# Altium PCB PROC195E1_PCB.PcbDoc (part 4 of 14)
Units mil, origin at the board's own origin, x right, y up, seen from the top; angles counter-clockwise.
Board outline 3110.24 x 2500 mil, 10 copper layers (Top Layer, L02_GND1, L03_SIG1, L04_GND2, L05_PWR1, L06_PWR2, L07_GND3, L08_SIG2, L09_GND4, Bottom Layer), stack 66.407 mil thick; 571 components, 538 nets, 6726 pads, 1286 vias.
Unrouted connection lines stored in the file: 4.
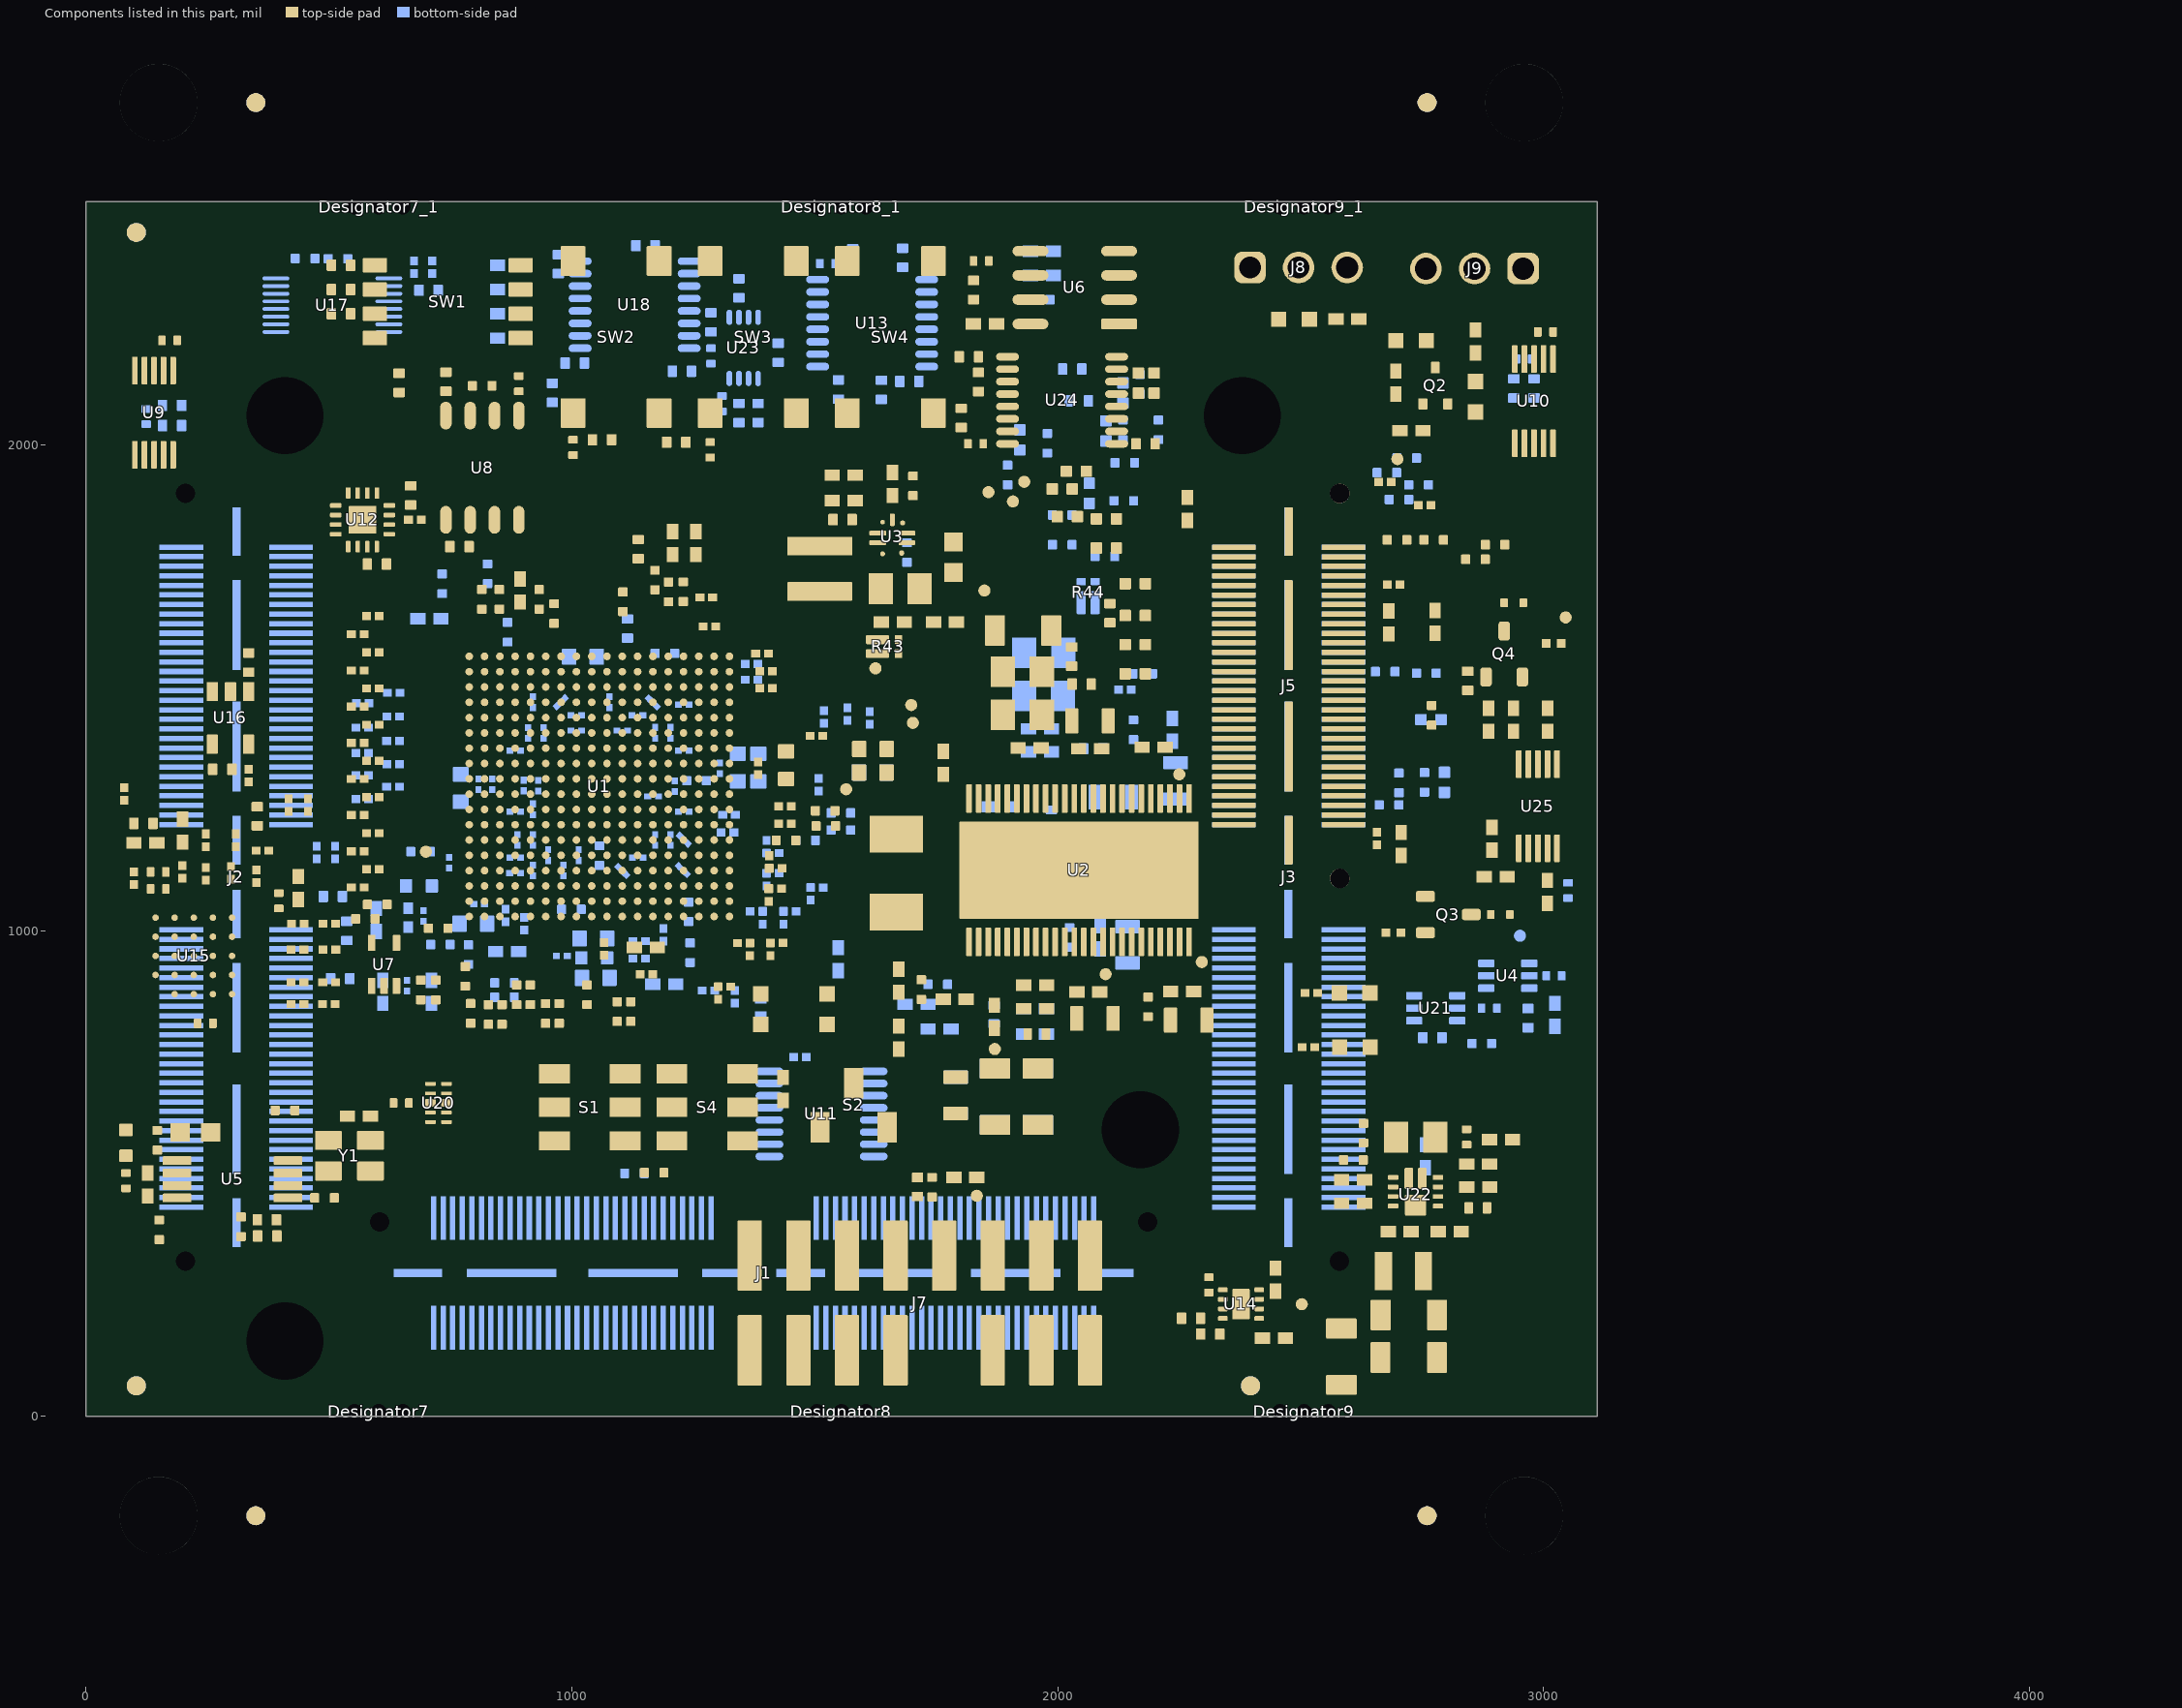
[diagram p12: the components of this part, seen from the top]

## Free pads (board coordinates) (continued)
  round 2.5 on Mech16: 1(163.27,426.27) 1(163.27,426.27) 1(163.27,432.27) 1(163.27,432.27) 1(163.27,445.96) 1(163.27,445.96) 1(163.27,451.96) 1(163.27,451.96) 1(163.27,465.65) 1(163.27,465.65) 1(163.27,471.65) 1(163.27,471.65) 1(163.27,485.34) 1(163.27,485.34) 1(163.27,491.34) 1(163.27,491.34) 1(163.27,505.03) 1(163.27,505.03) 1(163.27,511.03) 1(163.27,511.03) 1(163.27,524.72) 1(163.27,524.72) 1(163.27,530.72) 1(163.27,530.72) 1(163.27,544.41) 1(163.27,544.41) 1(163.27,550.41) 1(163.27,550.41) 1(163.27,564.1) 1(163.27,564.1) 1(163.27,570.1) 1(163.27,570.1) 1(163.27,583.79) 1(163.27,583.79) 1(163.27,589.79) 1(163.27,589.79) 1(163.27,603.48) 1(163.27,603.48) 1(163.27,603.53) 1(163.27,603.53) 1(163.27,609.48) 1(163.27,609.48) 1(163.27,609.53) 1(163.27,609.53) 1(163.27,623.17) 1(163.27,623.17) 1(163.27,629.17) 1(163.27,629.17) 1(163.27,642.86) 1(163.27,642.86) 1(163.27,648.86) 1(163.27,648.86) 1(163.27,662.55) 1(163.27,662.55) 1(163.27,668.55) 1(163.27,668.55) 1(163.27,682.24) 1(163.27,682.24) 1(163.27,688.24) 1(163.27,688.24) 1(163.27,701.93) 1(163.27,701.93) 1(163.27,707.93) 1(163.27,707.93) 1(163.27,721.62) 1(163.27,721.62) 1(163.27,727.62) 1(163.27,727.62) 1(163.27,741.31) 1(163.27,741.31) 1(163.27,747.31) 1(163.27,747.31) 1(163.27,761) 1(163.27,761) 1(163.27,767) 1(163.27,767) 1(163.27,780.69) 1(163.27,780.69) 1(163.27,786.69) 1(163.27,786.69) 1(163.27,800.38) 1(163.27,800.38) 1(163.27,806.38) 1(163.27,806.38) 1(163.27,820.07) 1(163.27,820.07) 1(163.27,826.07) 1(163.27,826.07) 1(163.27,839.76) 1(163.27,839.76) 1(163.27,845.76) 1(163.27,845.76) 1(163.27,859.45) 1(163.27,859.45) 1(163.27,865.45) 1(163.27,865.45) 1(163.27,879.14) 1(163.27,879.14) 1(163.27,885.14) 1(163.27,885.14) 1(163.27,898.83) 1(163.27,898.83) 1(163.27,904.83) 1(163.27,904.83) 1(163.27,918.52) 1(163.27,918.52) 1(163.27,924.52) 1(163.27,924.52) 1(163.27,938.21) 1(163.27,938.21) 1(163.27,944.21) 1(163.27,944.21) 1(163.27,957.9) 1(163.27,957.9) 1(163.27,963.9) 1(163.27,963.9) 1(163.27,977.59) 1(163.27,977.59) 1(163.27,983.59) 1(163.27,983.59) 1(163.27,997.28) 1(163.27,997.28) 1(163.27,1003.28) 1(163.27,1003.28) 1(163.27,1213.77) 1(163.27,1213.77) 1(163.27,1219.77) 1(163.27,1219.77) 1(163.27,1233.46) 1(163.27,1233.46) 1(163.27,1239.46) 1(163.27,1239.46) 1(163.27,1253.15) 1(163.27,1253.15) 1(163.27,1259.15) 1(163.27,1259.15) 1(163.27,1272.84) 1(163.27,1272.84) 1(163.27,1278.84) 1(163.27,1278.84) 1(163.27,1292.53) 1(163.27,1292.53) 1(163.27,1298.53) 1(163.27,1298.53) 1(163.27,1312.22) 1(163.27,1312.22) 1(163.27,1318.22) 1(163.27,1318.22) 1(163.27,1331.91) 1(163.27,1331.91) 1(163.27,1337.91) 1(163.27,1337.91) 1(163.27,1351.6) 1(163.27,1351.6) 1(163.27,1357.6) 1(163.27,1357.6) 1(163.27,1371.29) 1(163.27,1371.29) 1(163.27,1377.29) 1(163.27,1377.29) 1(163.27,1390.98) 1(163.27,1390.98) 1(163.27,1396.98) 1(163.27,1396.98) 1(163.27,1410.67) 1(163.27,1410.67) 1(163.27,1416.67) 1(163.27,1416.67) 1(163.27,1430.36) 1(163.27,1430.36) 1(163.27,1436.36) 1(163.27,1436.36) 1(163.27,1450.05) 1(163.27,1450.05) 1(163.27,1456.05) 1(163.27,1456.05) 1(163.27,1469.74) 1(163.27,1469.74) 1(163.27,1475.74) 1(163.27,1475.74) 1(163.27,1489.43) 1(163.27,1489.43) 1(163.27,1495.43) 1(163.27,1495.43) 1(163.27,1509.12) 1(163.27,1509.12) 1(163.27,1515.12) 1(163.27,1515.12) 1(163.27,1528.81) 1(163.27,1528.81) 1(163.27,1534.81) 1(163.27,1534.81) 1(163.27,1548.5) 1(163.27,1548.5) 1(163.27,1554.5) 1(163.27,1554.5) 1(163.27,1568.19) 1(163.27,1568.19) 1(163.27,1574.19) 1(163.27,1574.19) 1(163.27,1587.88) 1(163.27,1587.88) 1(163.27,1593.88) 1(163.27,1593.88) 1(163.27,1607.57) 1(163.27,1607.57) 1(163.27,1613.57) 1(163.27,1613.57) 1(163.27,1627.26) 1(163.27,1627.26) 1(163.27,1633.26) 1(163.27,1633.26) 1(163.27,1646.95) 1(163.27,1646.95) 1(163.27,1652.95) 1(163.27,1652.95) 1(163.27,1666.64) 1(163.27,1666.64) 1(163.27,1672.64) 1(163.27,1672.64) 1(163.27,1686.33) 1(163.27,1686.33) 1(163.27,1692.33) 1(163.27,1692.33) 1(163.27,1706.02) 1(163.27,1706.02) 1(163.27,1712.02) 1(163.27,1712.02) 1(163.27,1725.71) 1(163.27,1725.71) 1(163.27,1731.71) 1(163.27,1731.71) 1(163.27,1745.4) 1(163.27,1745.4) 1(163.27,1751.4) 1(163.27,1751.4) 1(163.27,1765.09) 1(163.27,1765.09) 1(163.27,1771.09) 1(163.27,1771.09) 1(163.27,1784.78) 1(163.27,1784.78) 1(163.27,1790.78) 1(163.27,1790.78) 1(168.27,296.02) 1(168.27,296.02) 1(168.27,426.27) 1(168.27,432.27) 1(168.27,445.96) 1(168.27,451.96) 1(168.27,465.65) 1(168.27,471.65) 1(168.27,485.34) 1(168.27,491.34) 1(168.27,505.03) 1(168.27,511.03) 1(168.27,524.72) 1(168.27,530.72) 1(168.27,544.41) 1(168.27,550.41) 1(168.27,564.1) 1(168.27,570.1) 1(168.27,583.79) 1(168.27,589.79) 1(168.27,603.48) 1(168.27,603.53) 1(168.27,609.48) 1(168.27,609.53) 1(168.27,623.17) 1(168.27,629.17) 1(168.27,642.86) 1(168.27,648.86) 1(168.27,662.55) 1(168.27,668.55) 1(168.27,682.24) 1(168.27,688.24) 1(168.27,701.93) 1(168.27,707.93) 1(168.27,721.62) 1(168.27,727.62) 1(168.27,741.31) 1(168.27,747.31) 1(168.27,761) 1(168.27,767) 1(168.27,780.69) 1(168.27,786.69) 1(168.27,800.38) 1(168.27,806.38) 1(168.27,820.07) 1(168.27,826.07) 1(168.27,839.76) 1(168.27,845.76) 1(168.27,859.45) 1(168.27,865.45) 1(168.27,879.14) 1(168.27,885.14) 1(168.27,898.83) 1(168.27,904.83) 1(168.27,918.52) 1(168.27,924.52) 1(168.27,938.21) 1(168.27,944.21) 1(168.27,957.9) 1(168.27,963.9) 1(168.27,977.59) 1(168.27,983.59) 1(168.27,997.28) 1(168.27,1003.28) 1(168.27,1213.77) 1(168.27,1219.77) 1(168.27,1233.46) 1(168.27,1239.46) 1(168.27,1253.15) 1(168.27,1259.15) 1(168.27,1272.84) 1(168.27,1278.84) 1(168.27,1292.53) 1(168.27,1298.53) 1(168.27,1312.22) 1(168.27,1318.22) 1(168.27,1331.91) 1(168.27,1337.91) 1(168.27,1351.6) 1(168.27,1357.6) 1(168.27,1371.29) 1(168.27,1377.29) 1(168.27,1390.98) 1(168.27,1396.98) 1(168.27,1410.67) 1(168.27,1416.67) 1(168.27,1430.36) 1(168.27,1436.36) 1(168.27,1450.05) 1(168.27,1456.05) 1(168.27,1469.74) 1(168.27,1475.74) 1(168.27,1489.43) 1(168.27,1495.43) 1(168.27,1509.12) 1(168.27,1515.12) 1(168.27,1528.81) 1(168.27,1534.81) 1(168.27,1548.5) 1(168.27,1554.5) 1(168.27,1568.19) 1(168.27,1574.19) 1(168.27,1587.88) 1(168.27,1593.88) 1(168.27,1607.57) 1(168.27,1613.57) 1(168.27,1627.26) 1(168.27,1633.26) 1(168.27,1646.95) 1(168.27,1652.95) 1(168.27,1666.64) 1(168.27,1672.64) 1(168.27,1686.33) 1(168.27,1692.33) 1(168.27,1706.02) 1(168.27,1712.02) 1(168.27,1725.71) 1(168.27,1731.71) 1(168.27,1745.4) 1(168.27,1751.4) 1(168.27,1765.09) 1(168.27,1771.09) 1(168.27,1784.78) 1(168.27,1790.78) 1(168.27,1921.02) 1(168.27,1921.02) 1(176.27,1852) 1(176.27,1852) 1(176.27,1913.02) 1(176.27,1913.02) 1(182.5,370.13) 1(182.5,370.13) 1(182.5,370.13) 1(182.5,1846.92) 1(182.5,1846.92) 1(182.5,1846.92) 1(188.27,372.52) 1(188.27,372.52) 1(188.27,372.52) 1(188.27,1844.52) 1(188.27,1844.52) 1(188.27,1844.52) 1(237.29,1913.02) 1(237.29,1913.02) 1(240.88,311.75) 1(240.88,311.75) 1(240.88,311.75) 1(240.88,1905.3) 1(240.88,1905.3) 1(240.88,1905.3) 1(243.27,317.52) 1(243.27,317.52) 1(243.27,317.52) 1(243.27,1899.52) 1(243.27,1899.52) 1(243.27,1899.52) 1(433.27,317.52) 1(433.27,317.52) 1(433.27,317.52) 1(433.27,1899.52) 1(433.27,1899.52) 1(433.27,1899.52) 1(439.04,311.75) 1(439.04,311.75) 1(439.04,311.75) 1(439.04,1905.3) 1(439.04,1905.3) 1(439.04,1905.3) 1(453.27,296.02) 1(453.27,296.02) 1(453.27,426.27) 1(453.27,432.27) 1(453.27,445.96) 1(453.27,451.96) 1(453.27,465.65) 1(453.27,471.65) 1(453.27,485.34) 1(453.27,491.34) 1(453.27,505.03) 1(453.27,511.03) 1(453.27,524.72) 1(453.27,530.72) 1(453.27,544.41) 1(453.27,550.41) 1(453.27,564.1) 1(453.27,570.1) 1(453.27,583.79) 1(453.27,589.79) 1(453.27,603.48) 1(453.27,603.53) 1(453.27,609.48) 1(453.27,609.53) 1(453.27,623.17) 1(453.27,629.17) 1(453.27,642.86) 1(453.27,648.86) 1(453.27,662.55) 1(453.27,668.55) 1(453.27,682.24) 1(453.27,688.24) 1(453.27,701.93) 1(453.27,707.93) 1(453.27,721.62) 1(453.27,727.62) 1(453.27,741.31) 1(453.27,747.31) 1(453.27,761) 1(453.27,767) 1(453.27,780.69) 1(453.27,786.69) 1(453.27,800.38) 1(453.27,806.38) 1(453.27,820.07) 1(453.27,826.07) 1(453.27,839.76) 1(453.27,845.76) 1(453.27,859.45) 1(453.27,865.45) 1(453.27,879.14) 1(453.27,885.14) 1(453.27,898.83) 1(453.27,904.83) 1(453.27,918.52) 1(453.27,924.52) 1(453.27,938.21) 1(453.27,944.21) 1(453.27,957.9) 1(453.27,963.9) 1(453.27,977.59) 1(453.27,983.59) 1(453.27,997.28) 1(453.27,1003.28) 1(453.27,1213.77) 1(453.27,1219.77) 1(453.27,1233.46) 1(453.27,1239.46) 1(453.27,1253.15) 1(453.27,1259.15) 1(453.27,1272.84) 1(453.27,1278.84) 1(453.27,1292.53) 1(453.27,1298.53) 1(453.27,1312.22) 1(453.27,1318.22) 1(453.27,1331.91) 1(453.27,1337.91) 1(453.27,1351.6) 1(453.27,1357.6) 1(453.27,1371.29) 1(453.27,1377.29) 1(453.27,1390.98) 1(453.27,1396.98) 1(453.27,1410.67) 1(453.27,1416.67) 1(453.27,1430.36) 1(453.27,1436.36) 1(453.27,1450.05) 1(453.27,1456.05) 1(453.27,1469.74) 1(453.27,1475.74) 1(453.27,1489.43) 1(453.27,1495.43) 1(453.27,1509.12) 1(453.27,1515.12) 1(453.27,1528.81) 1(453.27,1534.81) 1(453.27,1548.5) 1(453.27,1554.5) 1(453.27,1568.19) 1(453.27,1574.19) 1(453.27,1587.88) 1(453.27,1593.88) 1(453.27,1607.57) 1(453.27,1613.57) 1(453.27,1627.26) 1(453.27,1633.26) 1(453.27,1646.95) 1(453.27,1652.95) 1(453.27,1666.64) 1(453.27,1672.64) 1(453.27,1686.33) 1(453.27,1692.33) 1(453.27,1706.02) 1(453.27,1712.02) 1(453.27,1725.71) 1(453.27,1731.71) 1(453.27,1745.4) 1(453.27,1751.4) 1(453.27,1765.09) 1(453.27,1771.09) 1(453.27,1784.78) 1(453.27,1790.78) 1(453.27,1921.02) 1(453.27,1921.02) 1(458.27,426.27) 1(458.27,426.27) 1(458.27,432.27) 1(458.27,432.27) 1(458.27,445.96) 1(458.27,445.96) 1(458.27,451.96) 1(458.27,451.96) 1(458.27,465.65) 1(458.27,465.65) 1(458.27,471.65) 1(458.27,471.65) 1(458.27,485.34) 1(458.27,485.34) 1(458.27,491.34) 1(458.27,491.34) 1(458.27,505.03) 1(458.27,505.03) 1(458.27,511.03) 1(458.27,511.03) 1(458.27,524.72) 1(458.27,524.72) 1(458.27,530.72) 1(458.27,530.72) 1(458.27,544.41) 1(458.27,544.41) 1(458.27,550.41) 1(458.27,550.41) 1(458.27,564.1) 1(458.27,564.1) 1(458.27,570.1) 1(458.27,570.1) 1(458.27,583.79) 1(458.27,583.79) 1(458.27,589.79) 1(458.27,589.79) 1(458.27,603.48) 1(458.27,603.48) 1(458.27,603.53) 1(458.27,603.53) 1(458.27,609.48) 1(458.27,609.48) 1(458.27,609.53) 1(458.27,609.53) 1(458.27,623.17) 1(458.27,623.17) 1(458.27,629.17) 1(458.27,629.17) 1(458.27,642.86) 1(458.27,642.86) 1(458.27,648.86) 1(458.27,648.86) 1(458.27,662.55) 1(458.27,662.55) 1(458.27,668.55) 1(458.27,668.55) 1(458.27,682.24) 1(458.27,682.24) 1(458.27,688.24) 1(458.27,688.24) 1(458.27,701.93) 1(458.27,701.93) 1(458.27,707.93) 1(458.27,707.93) 1(458.27,721.62) 1(458.27,721.62) 1(458.27,727.62) 1(458.27,727.62) 1(458.27,741.31) 1(458.27,741.31) 1(458.27,747.31) 1(458.27,747.31) 1(458.27,761) 1(458.27,761) 1(458.27,767) 1(458.27,767) 1(458.27,780.69) 1(458.27,780.69) 1(458.27,786.69) 1(458.27,786.69) 1(458.27,800.38) 1(458.27,800.38) 1(458.27,806.38) 1(458.27,806.38) 1(458.27,820.07) 1(458.27,820.07) 1(458.27,826.07) 1(458.27,826.07) 1(458.27,839.76) 1(458.27,839.76) 1(458.27,845.76) 1(458.27,845.76) 1(458.27,859.45) 1(458.27,859.45) 1(458.27,865.45) 1(458.27,865.45) 1(458.27,879.14) 1(458.27,879.14) 1(458.27,885.14) 1(458.27,885.14) 1(458.27,898.83) 1(458.27,898.83) 1(458.27,904.83) 1(458.27,904.83) 1(458.27,918.52) 1(458.27,918.52) 1(458.27,924.52) 1(458.27,924.52) 1(458.27,938.21) 1(458.27,938.21) 1(458.27,944.21) 1(458.27,944.21) 1(458.27,957.9) 1(458.27,957.9) 1(458.27,963.9) 1(458.27,963.9) 1(458.27,977.59) 1(458.27,977.59) 1(458.27,983.59) 1(458.27,983.59) 1(458.27,997.28) 1(458.27,997.28) 1(458.27,1003.28) 1(458.27,1003.28) 1(458.27,1213.77) 1(458.27,1213.77) 1(458.27,1219.77) 1(458.27,1219.77) 1(458.27,1233.46) 1(458.27,1233.46) 1(458.27,1239.46) 1(458.27,1239.46) 1(458.27,1253.15) 1(458.27,1253.15) 1(458.27,1259.15) 1(458.27,1259.15) 1(458.27,1272.84) 1(458.27,1272.84) 1(458.27,1278.84) 1(458.27,1278.84) 1(458.27,1292.53) 1(458.27,1292.53) 1(458.27,1298.53) 1(458.27,1298.53) 1(458.27,1312.22) 1(458.27,1312.22) 1(458.27,1318.22) 1(458.27,1318.22) 1(458.27,1331.91) 1(458.27,1331.91) 1(458.27,1337.91) 1(458.27,1337.91) 1(458.27,1351.6) 1(458.27,1351.6) 1(458.27,1357.6) 1(458.27,1357.6) 1(458.27,1371.29) 1(458.27,1371.29) 1(458.27,1377.29) 1(458.27,1377.29) 1(458.27,1390.98) 1(458.27,1390.98) 1(458.27,1396.98) 1(458.27,1396.98) 1(458.27,1410.67) 1(458.27,1410.67) 1(458.27,1416.67) 1(458.27,1416.67) 1(458.27,1430.36) 1(458.27,1430.36) 1(458.27,1436.36) 1(458.27,1436.36) 1(458.27,1450.05) 1(458.27,1450.05) 1(458.27,1456.05) 1(458.27,1456.05) 1(458.27,1469.74) 1(458.27,1469.74) 1(458.27,1475.74) 1(458.27,1475.74) 1(458.27,1489.43) 1(458.27,1489.43) 1(458.27,1495.43) 1(458.27,1495.43) 1(458.27,1509.12) 1(458.27,1509.12) 1(458.27,1515.12) 1(458.27,1515.12) 1(458.27,1528.81) 1(458.27,1528.81) 1(458.27,1534.81) 1(458.27,1534.81) 1(458.27,1548.5) 1(458.27,1548.5) 1(458.27,1554.5) 1(458.27,1554.5) 1(458.27,1568.19) 1(458.27,1568.19) 1(458.27,1574.19) 1(458.27,1574.19) 1(458.27,1587.88) 1(458.27,1587.88) 1(458.27,1593.88) 1(458.27,1593.88) 1(458.27,1607.57) 1(458.27,1607.57) 1(458.27,1613.57) 1(458.27,1613.57) 1(458.27,1627.26) 1(458.27,1627.26) 1(458.27,1633.26) 1(458.27,1633.26) 1(458.27,1646.95) 1(458.27,1646.95) 1(458.27,1652.95) 1(458.27,1652.95) 1(458.27,1666.64) 1(458.27,1666.64) 1(458.27,1672.64) 1(458.27,1672.64) 1(458.27,1686.33) 1(458.27,1686.33) 1(458.27,1692.33) 1(458.27,1692.33) 1(458.27,1706.02) 1(458.27,1706.02) 1(458.27,1712.02) 1(458.27,1712.02) 1(458.27,1725.71) 1(458.27,1725.71) 1(458.27,1731.71) 1(458.27,1731.71) 1(458.27,1745.4) 1(458.27,1745.4) 1(458.27,1751.4) 1(458.27,1751.4) 1(458.27,1765.09) 1(458.27,1765.09) 1(458.27,1771.09) 1(458.27,1771.09) 1(458.27,1784.78) 1(458.27,1784.78) 1(458.27,1790.78) 1(458.27,1790.78) 1(581.02,151.73) 1(581.02,151.73) 1(581.02,436.73) 1(581.02,436.73) 1(581.02,1776.73) 1(581.02,1776.73) 1(581.02,2061.73) 1(581.02,2061.73) 1(596.75,165.96) 1(596.75,165.96) 1(596.75,165.96) 1(596.75,364.12) 1(596.75,364.12) 1(596.75,364.12) 1(596.75,1790.96) 1(596.75,1790.96) 1(596.75,1790.96) 1(596.75,1989.12) 1(596.75,1989.12) 1(596.75,1989.12) 1(602.52,171.73) 1(602.52,171.73) 1(602.52,171.73) 1(602.52,361.73) 1(602.52,361.73) 1(602.52,361.73) 1(602.52,1796.73) 1(602.52,1796.73) 1(602.52,1796.73) 1(602.52,1986.73) 1(602.52,1986.73) 1(602.52,1986.73) 1(655.13,422.51) 1(655.13,422.51) 1(655.13,422.51) 1(655.13,2047.51) 1(655.13,2047.51) 1(655.13,2047.51) 1(657.52,416.73) 1(657.52,416.73) 1(657.52,416.73) 1(657.52,2041.73) 1(657.52,2041.73) 1(657.52,2041.73) 1(711.27,146.73) 1(711.27,146.73) 1(711.27,151.73) 1(711.27,436.73) 1(711.27,441.73) 1(711.27,441.73) 1(711.27,1771.73) 1(711.27,1771.73) 1(711.27,1776.73) 1(711.27,2061.73) 1(711.27,2066.73) 1(711.27,2066.73) 1(717.27,146.73) 1(717.27,146.73) 1(717.27,151.73) 1(717.27,436.73) 1(717.27,441.73) 1(717.27,441.73) 1(717.27,1771.73) 1(717.27,1771.73) 1(717.27,1776.73) 1(717.27,2061.73) 1(717.27,2066.73) 1(717.27,2066.73) 1(730.96,146.73) 1(730.96,146.73) 1(730.96,151.73) 1(730.96,436.73) 1(730.96,441.73) 1(730.96,441.73) 1(730.96,1771.73) 1(730.96,1771.73) 1(730.96,1776.73) 1(730.96,2061.73) 1(730.96,2066.73) 1(730.96,2066.73) 1(736.96,146.73) 1(736.96,146.73) 1(736.96,151.73) 1(736.96,436.73) 1(736.96,441.73) 1(736.96,441.73) 1(736.96,1771.73) 1(736.96,1771.73) 1(736.96,1776.73) 1(736.96,2061.73) 1(736.96,2066.73) 1(736.96,2066.73) 1(750.65,146.73) 1(750.65,146.73) 1(750.65,151.73) 1(750.65,436.73) 1(750.65,441.73) 1(750.65,441.73) 1(750.65,1771.73) 1(750.65,1771.73) 1(750.65,1776.73) 1(750.65,2061.73) 1(750.65,2066.73) 1(750.65,2066.73) 1(756.65,146.73) 1(756.65,146.73) 1(756.65,151.73) 1(756.65,436.73) 1(756.65,441.73) 1(756.65,441.73) 1(756.65,1771.73) 1(756.65,1771.73) 1(756.65,1776.73) 1(756.65,2061.73) 1(756.65,2066.73) 1(756.65,2066.73) 1(770.34,146.73) 1(770.34,146.73) 1(770.34,151.73) 1(770.34,436.73) 1(770.34,441.73) 1(770.34,441.73) 1(770.34,1771.73) 1(770.34,1771.73) 1(770.34,1776.73) 1(770.34,2061.73) 1(770.34,2066.73) 1(770.34,2066.73) 1(776.34,146.73) 1(776.34,146.73) 1(776.34,151.73) 1(776.34,436.73) 1(776.34,441.73) 1(776.34,441.73) 1(776.34,1771.73) 1(776.34,1771.73) 1(776.34,1776.73) 1(776.34,2061.73) 1(776.34,2066.73) 1(776.34,2066.73) 1(790.03,146.73) 1(790.03,146.73) 1(790.03,151.73) 1(790.03,436.73) 1(790.03,441.73) 1(790.03,441.73) 1(790.03,1771.73) 1(790.03,1771.73) 1(790.03,1776.73) 1(790.03,2061.73) 1(790.03,2066.73) 1(790.03,2066.73) 1(796.03,146.73) 1(796.03,146.73) 1(796.03,151.73) 1(796.03,436.73) 1(796.03,441.73) 1(796.03,441.73) 1(796.03,1771.73) 1(796.03,1771.73) 1(796.03,1776.73) 1(796.03,2061.73) 1(796.03,2066.73) 1(796.03,2066.73) 1(809.72,146.73) 1(809.72,146.73) 1(809.72,151.73) 1(809.72,436.73) 1(809.72,441.73) 1(809.72,441.73) 1(809.72,1771.73) 1(809.72,1771.73) 1(809.72,1776.73) 1(809.72,2061.73) 1(809.72,2066.73) 1(809.72,2066.73) 1(815.72,146.73) 1(815.72,146.73) 1(815.72,151.73) 1(815.72,436.73) 1(815.72,441.73) 1(815.72,441.73) 1(815.72,1771.73) 1(815.72,1771.73) 1(815.72,1776.73) 1(815.72,2061.73) 1(815.72,2066.73) 1(815.72,2066.73) 1(829.41,146.73) 1(829.41,146.73) 1(829.41,151.73) 1(829.41,436.73) 1(829.41,441.73) 1(829.41,441.73) 1(829.41,1771.73) 1(829.41,1771.73) 1(829.41,1776.73) 1(829.41,2061.73) 1(829.41,2066.73) 1(829.41,2066.73) 1(835.41,146.73) 1(835.41,146.73) 1(835.41,151.73) 1(835.41,436.73) 1(835.41,441.73) 1(835.41,441.73) 1(835.41,1771.73) 1(835.41,1771.73) 1(835.41,1776.73) 1(835.41,2061.73) 1(835.41,2066.73) 1(835.41,2066.73) 1(849.1,146.73) 1(849.1,146.73) 1(849.1,151.73) 1(849.1,436.73) 1(849.1,441.73) 1(849.1,441.73) 1(849.1,1771.73) 1(849.1,1771.73) 1(849.1,1776.73) 1(849.1,2061.73) 1(849.1,2066.73) 1(849.1,2066.73) 1(855.1,146.73) 1(855.1,146.73) 1(855.1,151.73) 1(855.1,436.73) 1(855.1,441.73) 1(855.1,441.73) 1(855.1,1771.73) 1(855.1,1771.73) 1(855.1,1776.73) 1(855.1,2061.73) 1(855.1,2066.73) 1(855.1,2066.73) 1(868.79,146.73) 1(868.79,146.73) 1(868.79,151.73) 1(868.79,436.73) 1(868.79,441.73) 1(868.79,441.73) 1(868.79,1771.73) 1(868.79,1771.73) 1(868.79,1776.73) 1(868.79,2061.73) 1(868.79,2066.73) 1(868.79,2066.73) 1(874.79,146.73) 1(874.79,146.73) 1(874.79,151.73) 1(874.79,436.73) 1(874.79,441.73) 1(874.79,441.73) 1(874.79,1771.73) 1(874.79,1771.73) 1(874.79,1776.73) 1(874.79,2061.73) 1(874.79,2066.73) 1(874.79,2066.73) 1(888.48,146.73) 1(888.48,146.73) 1(888.48,151.73) 1(888.48,436.73) 1(888.48,441.73) 1(888.48,441.73) 1(888.48,1771.73) 1(888.48,1771.73) 1(888.48,1776.73) 1(888.48,2061.73) 1(888.48,2066.73) 1(888.48,2066.73) 1(888.53,146.73) 1(888.53,146.73) 1(888.53,151.73) 1(888.53,436.73) 1(888.53,441.73) 1(888.53,441.73) 1(888.53,1771.73) 1(888.53,1771.73) 1(888.53,1776.73) 1(888.53,2061.73) 1(888.53,2066.73) 1(888.53,2066.73) 1(894.48,146.73) 1(894.48,146.73) 1(894.48,151.73) 1(894.48,436.73) 1(894.48,441.73) 1(894.48,441.73) 1(894.48,1771.73) 1(894.48,1771.73) 1(894.48,1776.73) 1(894.48,2061.73) 1(894.48,2066.73) 1(894.48,2066.73) 1(894.53,146.73) 1(894.53,146.73) 1(894.53,151.73) 1(894.53,436.73) 1(894.53,441.73) 1(894.53,441.73) 1(894.53,1771.73) 1(894.53,1771.73) 1(894.53,1776.73) 1(894.53,2061.73) 1(894.53,2066.73) 1(894.53,2066.73) 1(908.17,146.73) 1(908.17,146.73) 1(908.17,151.73) 1(908.17,436.73) 1(908.17,441.73) 1(908.17,441.73) 1(908.17,1771.73) 1(908.17,1771.73) 1(908.17,1776.73) 1(908.17,2061.73) 1(908.17,2066.73) 1(908.17,2066.73) 1(914.17,146.73) 1(914.17,146.73) 1(914.17,151.73) 1(914.17,436.73) 1(914.17,441.73) 1(914.17,441.73) 1(914.17,1771.73) 1(914.17,1771.73) 1(914.17,1776.73) 1(914.17,2061.73) 1(914.17,2066.73) 1(914.17,2066.73) 1(927.86,146.73) 1(927.86,146.73) 1(927.86,151.73) 1(927.86,436.73) 1(927.86,441.73) 1(927.86,441.73) 1(927.86,1771.73) 1(927.86,1771.73) 1(927.86,1776.73) 1(927.86,2061.73) 1(927.86,2066.73) 1(927.86,2066.73) 1(933.86,146.73) 1(933.86,146.73) 1(933.86,151.73) 1(933.86,436.73) 1(933.86,441.73) 1(933.86,441.73) 1(933.86,1771.73) 1(933.86,1771.73) 1(933.86,1776.73) 1(933.86,2061.73) 1(933.86,2066.73) 1(933.86,2066.73) 1(947.55,146.73) 1(947.55,146.73) 1(947.55,151.73) 1(947.55,436.73) 1(947.55,441.73) 1(947.55,441.73) 1(947.55,1771.73) 1(947.55,1771.73) 1(947.55,1776.73) 1(947.55,2061.73) 1(947.55,2066.73) 1(947.55,2066.73) 1(953.55,146.73) 1(953.55,146.73) 1(953.55,151.73) 1(953.55,436.73) 1(953.55,441.73) 1(953.55,441.73) 1(953.55,1771.73) 1(953.55,1771.73) 1(953.55,1776.73) 1(953.55,2061.73) 1(953.55,2066.73) 1(953.55,2066.73) 1(967.24,146.73) 1(967.24,146.73) 1(967.24,151.73) 1(967.24,436.73) 1(967.24,441.73) 1(967.24,441.73) 1(967.24,1771.73) 1(967.24,1771.73) 1(967.24,1776.73) 1(967.24,2061.73) 1(967.24,2066.73) 1(967.24,2066.73) 1(973.24,146.73) 1(973.24,146.73) 1(973.24,151.73) 1(973.24,436.73) 1(973.24,441.73) 1(973.24,441.73) 1(973.24,1771.73) 1(973.24,1771.73) 1(973.24,1776.73) 1(973.24,2061.73) 1(973.24,2066.73) 1(973.24,2066.73) 1(986.93,146.73) 1(986.93,146.73) 1(986.93,151.73) 1(986.93,436.73) 1(986.93,441.73) 1(986.93,441.73) 1(986.93,1771.73) 1(986.93,1771.73) 1(986.93,1776.73) 1(986.93,2061.73) 1(986.93,2066.73) 1(986.93,2066.73) 1(992.93,146.73) 1(992.93,146.73) 1(992.93,151.73) 1(992.93,436.73) 1(992.93,441.73) 1(992.93,441.73) 1(992.93,1771.73) 1(992.93,1771.73) 1(992.93,1776.73) 1(992.93,2061.73) 1(992.93,2066.73) 1(992.93,2066.73) 1(1006.62,146.73) 1(1006.62,146.73) 1(1006.62,151.73) 1(1006.62,436.73) 1(1006.62,441.73) 1(1006.62,441.73) 1(1006.62,1771.73) 1(1006.62,1771.73) 1(1006.62,1776.73) 1(1006.62,2061.73) 1(1006.62,2066.73) 1(1006.62,2066.73) 1(1012.62,146.73) 1(1012.62,146.73) 1(1012.62,151.73) 1(1012.62,436.73) 1(1012.62,441.73) 1(1012.62,441.73) 1(1012.62,1771.73) 1(1012.62,1771.73) 1(1012.62,1776.73) 1(1012.62,2061.73) 1(1012.62,2066.73) 1(1012.62,2066.73) 1(1026.31,146.73) 1(1026.31,146.73) 1(1026.31,151.73) 1(1026.31,436.73) 1(1026.31,441.73) 1(1026.31,441.73) 1(1026.31,1771.73) 1(1026.31,1771.73) 1(1026.31,1776.73) 1(1026.31,2061.73) 1(1026.31,2066.73) 1(1026.31,2066.73) 1(1032.31,146.73) 1(1032.31,146.73) 1(1032.31,151.73) 1(1032.31,436.73) 1(1032.31,441.73) 1(1032.31,441.73) 1(1032.31,1771.73) 1(1032.31,1771.73) 1(1032.31,1776.73) 1(1032.31,2061.73) 1(1032.31,2066.73) 1(1032.31,2066.73) 1(1046,146.73) 1(1046,146.73) 1(1046,151.73) 1(1046,436.73) 1(1046,441.73) 1(1046,441.73) 1(1046,1771.73) 1(1046,1771.73) 1(1046,1776.73) 1(1046,2061.73) 1(1046,2066.73) 1(1046,2066.73) 1(1052,146.73) 1(1052,146.73) 1(1052,151.73) 1(1052,436.73) 1(1052,441.73) 1(1052,441.73) 1(1052,1771.73) 1(1052,1771.73) 1(1052,1776.73) 1(1052,2061.73) 1(1052,2066.73) 1(1052,2066.73) 1(1065.69,146.73) 1(1065.69,146.73) 1(1065.69,151.73) 1(1065.69,436.73) 1(1065.69,441.73) 1(1065.69,441.73) 1(1065.69,1771.73) 1(1065.69,1771.73) 1(1065.69,1776.73) 1(1065.69,2061.73) 1(1065.69,2066.73) 1(1065.69,2066.73) 1(1071.69,146.73) 1(1071.69,146.73) 1(1071.69,151.73) 1(1071.69,436.73) 1(1071.69,441.73) 1(1071.69,441.73) 1(1071.69,1771.73) 1(1071.69,1771.73) 1(1071.69,1776.73) 1(1071.69,2061.73) 1(1071.69,2066.73) 1(1071.69,2066.73) 1(1085.38,146.73) 1(1085.38,146.73) 1(1085.38,151.73) 1(1085.38,436.73) 1(1085.38,441.73) 1(1085.38,441.73) 1(1085.38,1771.73) 1(1085.38,1771.73) 1(1085.38,1776.73) 1(1085.38,2061.73) 1(1085.38,2066.73) 1(1085.38,2066.73) 1(1091.38,146.73) 1(1091.38,146.73) 1(1091.38,151.73) 1(1091.38,436.73) 1(1091.38,441.73) 1(1091.38,441.73) 1(1091.38,1771.73) 1(1091.38,1771.73) 1(1091.38,1776.73) 1(1091.38,2061.73) 1(1091.38,2066.73) 1(1091.38,2066.73) 1(1105.07,146.73) 1(1105.07,146.73) 1(1105.07,151.73) 1(1105.07,436.73) 1(1105.07,441.73) 1(1105.07,441.73) 1(1105.07,1771.73) 1(1105.07,1771.73) 1(1105.07,1776.73) 1(1105.07,2061.73) 1(1105.07,2066.73) 1(1105.07,2066.73) 1(1111.07,146.73) 1(1111.07,146.73) 1(1111.07,151.73) 1(1111.07,436.73) 1(1111.07,441.73) 1(1111.07,441.73) 1(1111.07,1771.73) 1(1111.07,1771.73) 1(1111.07,1776.73) 1(1111.07,2061.73) 1(1111.07,2066.73) 1(1111.07,2066.73) 1(1124.76,146.73) 1(1124.76,146.73) 1(1124.76,151.73) 1(1124.76,436.73) 1(1124.76,441.73) 1(1124.76,441.73) 1(1124.76,1771.73) 1(1124.76,1771.73) 1(1124.76,1776.73) 1(1124.76,2061.73) 1(1124.76,2066.73) 1(1124.76,2066.73) 1(1130.76,146.73) 1(1130.76,146.73) 1(1130.76,151.73) 1(1130.76,436.73) 1(1130.76,441.73) 1(1130.76,441.73) 1(1130.76,1771.73) 1(1130.76,1771.73) 1(1130.76,1776.73) 1(1130.76,2061.73) 1(1130.76,2066.73) 1(1130.76,2066.73) 1(1144.45,146.73) 1(1144.45,146.73) 1(1144.45,151.73) 1(1144.45,436.73) 1(1144.45,441.73) 1(1144.45,441.73) 1(1144.45,1771.73) 1(1144.45,1771.73) 1(1144.45,1776.73) 1(1144.45,2061.73) 1(1144.45,2066.73) 1(1144.45,2066.73) 1(1150.45,146.73) 1(1150.45,146.73) 1(1150.45,151.73) 1(1150.45,436.73) 1(1150.45,441.73) 1(1150.45,441.73) 1(1150.45,1771.73) 1(1150.45,1771.73) 1(1150.45,1776.73) 1(1150.45,2061.73) 1(1150.45,2066.73) 1(1150.45,2066.73) 1(1164.14,146.73) 1(1164.14,146.73) 1(1164.14,151.73) 1(1164.14,436.73) 1(1164.14,441.73) 1(1164.14,441.73) 1(1164.14,1771.73) 1(1164.14,1771.73) 1(1164.14,1776.73) 1(1164.14,2061.73) 1(1164.14,2066.73) 1(1164.14,2066.73) 1(1170.14,146.73) 1(1170.14,146.73) 1(1170.14,151.73) 1(1170.14,436.73) 1(1170.14,441.73) 1(1170.14,441.73) 1(1170.14,1771.73) 1(1170.14,1771.73) 1(1170.14,1776.73) 1(1170.14,2061.73) 1(1170.14,2066.73) 1(1170.14,2066.73) 1(1183.83,146.73) 1(1183.83,146.73) 1(1183.83,151.73) 1(1183.83,436.73) 1(1183.83,441.73) 1(1183.83,441.73) 1(1183.83,1771.73) 1(1183.83,1771.73) 1(1183.83,1776.73) 1(1183.83,2061.73) 1(1183.83,2066.73) 1(1183.83,2066.73) 1(1189.83,146.73) 1(1189.83,146.73) 1(1189.83,151.73) 1(1189.83,436.73) 1(1189.83,441.73) 1(1189.83,441.73) 1(1189.83,1771.73) 1(1189.83,1771.73) 1(1189.83,1776.73) 1(1189.83,2061.73) 1(1189.83,2066.73) 1(1189.83,2066.73) 1(1203.52,146.73) 1(1203.52,146.73) 1(1203.52,151.73) 1(1203.52,436.73) 1(1203.52,441.73) 1(1203.52,441.73) 1(1203.52,1771.73) 1(1203.52,1771.73) 1(1203.52,1776.73) 1(1203.52,2061.73) 1(1203.52,2066.73) 1(1203.52,2066.73) 1(1209.52,146.73) 1(1209.52,146.73) 1(1209.52,151.73) 1(1209.52,436.73) 1(1209.52,441.73) 1(1209.52,441.73) 1(1209.52,1771.73) 1(1209.52,1771.73) 1(1209.52,1776.73) 1(1209.52,2061.73) 1(1209.52,2066.73) 1(1209.52,2066.73) 1(1223.21,146.73) 1(1223.21,146.73) 1(1223.21,151.73) 1(1223.21,436.73) 1(1223.21,441.73) 1(1223.21,441.73) 1(1223.21,1771.73) 1(1223.21,1771.73) 1(1223.21,1776.73) 1(1223.21,2061.73) 1(1223.21,2066.73) 1(1223.21,2066.73) 1(1229.21,146.73) 1(1229.21,146.73) 1(1229.21,151.73) 1(1229.21,436.73) 1(1229.21,441.73) 1(1229.21,441.73) 1(1229.21,1771.73) 1(1229.21,1771.73) 1(1229.21,1776.73) 1(1229.21,2061.73) 1(1229.21,2066.73) 1(1229.21,2066.73) 1(1242.9,146.73) 1(1242.9,146.73) 1(1242.9,151.73) 1(1242.9,436.73) 1(1242.9,441.73) 1(1242.9,441.73) 1(1242.9,1771.73) 1(1242.9,1771.73) 1(1242.9,1776.73) 1(1242.9,2061.73) 1(1242.9,2066.73) 1(1242.9,2066.73) 1(1248.9,146.73) 1(1248.9,146.73) 1(1248.9,151.73) 1(1248.9,436.73) 1(1248.9,441.73) 1(1248.9,441.73) 1(1248.9,1771.73) 1(1248.9,1771.73) 1(1248.9,1776.73) 1(1248.9,2061.73) 1(1248.9,2066.73) 1(1248.9,2066.73) 1(1262.59,146.73) 1(1262.59,146.73) 1(1262.59,151.73) 1(1262.59,436.73) 1(1262.59,441.73) 1(1262.59,441.73) 1(1262.59,1771.73) 1(1262.59,1771.73) 1(1262.59,1776.73) 1(1262.59,2061.73) 1(1262.59,2066.73) 1(1262.59,2066.73) 1(1268.59,146.73) 1(1268.59,146.73) 1(1268.59,151.73) 1(1268.59,436.73) 1(1268.59,441.73) 1(1268.59,441.73) 1(1268.59,1771.73) 1(1268.59,1771.73) 1(1268.59,1776.73) 1(1268.59,2061.73) 1(1268.59,2066.73) 1(1268.59,2066.73) 1(1282.28,146.73) 1(1282.28,146.73) 1(1282.28,151.73) 1(1282.28,436.73) 1(1282.28,441.73) 1(1282.28,441.73) 1(1282.28,1771.73) 1(1282.28,1771.73) 1(1282.28,1776.73) 1(1282.28,2061.73) 1(1282.28,2066.73) 1(1282.28,2066.73) 1(1288.28,146.73) 1(1288.28,146.73) 1(1288.28,151.73) 1(1288.28,436.73) 1(1288.28,441.73) 1(1288.28,441.73) 1(1288.28,1771.73) 1(1288.28,1771.73) 1(1288.28,1776.73) 1(1288.28,2061.73) 1(1288.28,2066.73) 1(1288.28,2066.73) 1(1498.77,146.73) 1(1498.77,146.73) 1(1498.77,151.73) 1(1498.77,436.73) 1(1498.77,441.73) 1(1498.77,441.73) 1(1498.77,1771.73) 1(1498.77,1771.73) 1(1498.77,1776.73) 1(1498.77,2061.73) 1(1498.77,2066.73) 1(1498.77,2066.73) 1(1504.77,146.73) 1(1504.77,146.73) 1(1504.77,151.73) 1(1504.77,436.73) 1(1504.77,441.73) 1(1504.77,441.73) 1(1504.77,1771.73) 1(1504.77,1771.73) 1(1504.77,1776.73) 1(1504.77,2061.73) 1(1504.77,2066.73) 1(1504.77,2066.73) 1(1518.46,146.73) 1(1518.46,146.73) 1(1518.46,151.73) 1(1518.46,436.73) 1(1518.46,441.73) 1(1518.46,441.73) 1(1518.46,1771.73) 1(1518.46,1771.73) 1(1518.46,1776.73) 1(1518.46,2061.73) 1(1518.46,2066.73) 1(1518.46,2066.73) 1(1524.46,146.73) 1(1524.46,146.73) 1(1524.46,151.73) 1(1524.46,436.73) 1(1524.46,441.73) 1(1524.46,441.73) 1(1524.46,1771.73) 1(1524.46,1771.73) 1(1524.46,1776.73) 1(1524.46,2061.73) 1(1524.46,2066.73) 1(1524.46,2066.73) 1(1538.15,146.73) 1(1538.15,146.73) 1(1538.15,151.73) 1(1538.15,436.73) 1(1538.15,441.73) 1(1538.15,441.73) 1(1538.15,1771.73) 1(1538.15,1771.73) 1(1538.15,1776.73) 1(1538.15,2061.73) 1(1538.15,2066.73) 1(1538.15,2066.73) 1(1544.15,146.73) 1(1544.15,146.73) 1(1544.15,151.73) 1(1544.15,436.73) 1(1544.15,441.73) 1(1544.15,441.73) 1(1544.15,1771.73) 1(1544.15,1771.73) 1(1544.15,1776.73) 1(1544.15,2061.73) 1(1544.15,2066.73) 1(1544.15,2066.73) 1(1557.84,146.73) 1(1557.84,146.73) 1(1557.84,151.73) 1(1557.84,436.73) 1(1557.84,441.73) 1(1557.84,441.73) 1(1557.84,1771.73) 1(1557.84,1771.73) 1(1557.84,1776.73) 1(1557.84,2061.73) 1(1557.84,2066.73) 1(1557.84,2066.73) 1(1563.84,146.73) 1(1563.84,146.73) 1(1563.84,151.73) 1(1563.84,436.73) 1(1563.84,441.73) 1(1563.84,441.73) 1(1563.84,1771.73) 1(1563.84,1771.73) 1(1563.84,1776.73) 1(1563.84,2061.73) 1(1563.84,2066.73) 1(1563.84,2066.73) 1(1577,869) 1(1577,869) 1(1577,949) 1(1577,949) 1(1577.53,146.73) 1(1577.53,146.73) 1(1577.53,151.73) 1(1577.53,436.73) 1(1577.53,441.73) 1(1577.53,441.73) 1(1577.53,1771.73) 1(1577.53,1771.73) 1(1577.53,1776.73) 1(1577.53,2061.73) 1(1577.53,2066.73) 1(1577.53,2066.73) 1(1578,955) 1(1578,955) 1(1578,1035) 1(1578,1035) 1(1579,1042) 1(1579,1042) 1(1579,1122) 1(1579,1122) 1(1583.53,146.73) 1(1583.53,146.73) 1(1583.53,151.73) 1(1583.53,436.73) 1(1583.53,441.73) 1(1583.53,441.73) 1(1583.53,1771.73) 1(1583.53,1771.73) 1(1583.53,1776.73) 1(1583.53,2061.73) 1(1583.53,2066.73) 1(1583.53,2066.73) 1(1597.22,146.73) 1(1597.22,146.73) 1(1597.22,151.73) 1(1597.22,436.73) 1(1597.22,441.73) 1(1597.22,441.73) 1(1597.22,1771.73) 1(1597.22,1771.73) 1(1597.22,1776.73) 1(1597.22,2061.73) 1(1597.22,2066.73) 1(1597.22,2066.73) 1(1603.22,146.73) 1(1603.22,146.73) 1(1603.22,151.73) 1(1603.22,436.73) 1(1603.22,441.73) 1(1603.22,441.73) 1(1603.22,1771.73) 1(1603.22,1771.73) 1(1603.22,1776.73) 1(1603.22,2061.73) 1(1603.22,2066.73) 1(1603.22,2066.73) 1(1616.91,146.73) 1(1616.91,146.73) 1(1616.91,151.73) 1(1616.91,436.73) 1(1616.91,441.73) 1(1616.91,441.73) 1(1616.91,1771.73) 1(1616.91,1771.73) 1(1616.91,1776.73) 1(1616.91,2061.73) 1(1616.91,2066.73) 1(1616.91,2066.73) 1(1622.91,146.73) 1(1622.91,146.73) 1(1622.91,151.73) 1(1622.91,436.73) 1(1622.91,441.73) 1(1622.91,441.73) 1(1622.91,1771.73) 1(1622.91,1771.73) 1(1622.91,1776.73) 1(1622.91,2061.73) 1(1622.91,2066.73) 1(1622.91,2066.73) 1(1636.6,146.73) 1(1636.6,146.73) 1(1636.6,151.73) 1(1636.6,436.73) 1(1636.6,441.73) 1(1636.6,441.73) 1(1636.6,1771.73) 1(1636.6,1771.73) 1(1636.6,1776.73) 1(1636.6,2061.73) 1(1636.6,2066.73) 1(1636.6,2066.73) 1(1642.6,146.73) 1(1642.6,146.73) 1(1642.6,151.73) 1(1642.6,436.73) 1(1642.6,441.73) 1(1642.6,441.73) 1(1642.6,1771.73) 1(1642.6,1771.73) 1(1642.6,1776.73) 1(1642.6,2061.73) 1(1642.6,2066.73) 1(1642.6,2066.73) 1(1656.29,146.73) 1(1656.29,146.73) 1(1656.29,151.73) 1(1656.29,436.73) 1(1656.29,441.73) 1(1656.29,441.73) 1(1656.29,1771.73) 1(1656.29,1771.73) 1(1656.29,1776.73) 1(1656.29,2061.73) 1(1656.29,2066.73) 1(1656.29,2066.73) 1(1662.29,146.73) 1(1662.29,146.73) 1(1662.29,151.73) 1(1662.29,436.73) 1(1662.29,441.73) 1(1662.29,441.73) 1(1662.29,1771.73) 1(1662.29,1771.73) 1(1662.29,1776.73) 1(1662.29,2061.73) 1(1662.29,2066.73) 1(1662.29,2066.73) 1(1675.98,146.73) 1(1675.98,146.73) 1(1675.98,151.73) 1(1675.98,436.73) 1(1675.98,441.73) 1(1675.98,441.73) 1(1675.98,1771.73) 1(1675.98,1771.73) 1(1675.98,1776.73) 1(1675.98,2061.73) 1(1675.98,2066.73) 1(1675.98,2066.73) 1(1681.98,146.73) 1(1681.98,146.73) 1(1681.98,151.73) 1(1681.98,436.73) 1(1681.98,441.73) 1(1681.98,441.73) 1(1681.98,1771.73) 1(1681.98,1771.73) 1(1681.98,1776.73) 1(1681.98,2061.73) 1(1681.98,2066.73) 1(1681.98,2066.73) 1(1695.67,146.73) 1(1695.67,146.73) 1(1695.67,151.73) 1(1695.67,436.73) 1(1695.67,441.73) 1(1695.67,441.73) 1(1695.67,1771.73) 1(1695.67,1771.73) 1(1695.67,1776.73) 1(1695.67,2061.73) 1(1695.67,2066.73) 1(1695.67,2066.73) 1(1701.67,146.73) 1(1701.67,146.73) 1(1701.67,151.73) 1(1701.67,436.73) 1(1701.67,441.73) 1(1701.67,441.73) 1(1701.67,1771.73) 1(1701.67,1771.73) 1(1701.67,1776.73) 1(1701.67,2061.73) 1(1701.67,2066.73) 1(1701.67,2066.73) 1(1715.36,146.73) 1(1715.36,146.73) 1(1715.36,151.73) 1(1715.36,436.73) 1(1715.36,441.73) 1(1715.36,441.73) 1(1715.36,1771.73) 1(1715.36,1771.73) 1(1715.36,1776.73) 1(1715.36,2061.73) 1(1715.36,2066.73) 1(1715.36,2066.73) 1(1721.36,146.73) 1(1721.36,146.73) 1(1721.36,151.73) 1(1721.36,436.73) 1(1721.36,441.73) 1(1721.36,441.73) 1(1721.36,1771.73) 1(1721.36,1771.73) 1(1721.36,1776.73) 1(1721.36,2061.73) 1(1721.36,2066.73) 1(1721.36,2066.73) 1(1725,869) 1(1725,869) 1(1725,949) 1(1725,949) 1(1726,955) 1(1726,955) 1(1726,1035) 1(1726,1035) 1(1727,1042) 1(1727,1042) 1(1727,1122) 1(1727,1122) 1(1735.05,146.73) 1(1735.05,146.73) 1(1735.05,151.73) 1(1735.05,436.73) 1(1735.05,441.73) 1(1735.05,441.73) 1(1735.05,1771.73) 1(1735.05,1771.73) 1(1735.05,1776.73) 1(1735.05,2061.73) 1(1735.05,2066.73) 1(1735.05,2066.73) 1(1741.05,146.73) 1(1741.05,146.73) 1(1741.05,151.73) 1(1741.05,436.73) 1(1741.05,441.73) 1(1741.05,441.73) 1(1741.05,1771.73) 1(1741.05,1771.73) 1(1741.05,1776.73) 1(1741.05,2061.73) 1(1741.05,2066.73) 1(1741.05,2066.73) 1(1746,970) 1(1746,970) 1(1746,1050) 1(1746,1050) 1(1754.74,146.73) 1(1754.74,146.73) 1(1754.74,151.73) 1(1754.74,436.73) 1(1754.74,441.73) 1(1754.74,441.73) 1(1754.74,1771.73) 1(1754.74,1771.73) 1(1754.74,1776.73) 1(1754.74,2061.73) 1(1754.74,2066.73) 1(1754.74,2066.73) 1(1760.74,146.73) 1(1760.74,146.73) 1(1760.74,151.73) 1(1760.74,436.73) 1(1760.74,441.73) 1(1760.74,441.73) 1(1760.74,1771.73) 1(1760.74,1771.73) 1(1760.74,1776.73) 1(1760.74,2061.73) 1(1760.74,2066.73) 1(1760.74,2066.73) 1(1774.43,146.73) 1(1774.43,146.73) 1(1774.43,151.73) 1(1774.43,436.73) 1(1774.43,441.73) 1(1774.43,441.73) 1(1774.43,1771.73) 1(1774.43,1771.73) 1(1774.43,1776.73) 1(1774.43,2061.73) 1(1774.43,2066.73) 1(1774.43,2066.73) 1(1780.43,146.73) 1(1780.43,146.73) 1(1780.43,151.73) 1(1780.43,436.73) 1(1780.43,441.73) 1(1780.43,441.73) 1(1780.43,1771.73) 1(1780.43,1771.73) 1(1780.43,1776.73) 1(1780.43,2061.73) 1(1780.43,2066.73) 1(1780.43,2066.73) 1(1794.12,146.73) 1(1794.12,146.73) 1(1794.12,151.73) 1(1794.12,436.73) 1(1794.12,441.73) 1(1794.12,441.73) 1(1794.12,1771.73) 1(1794.12,1771.73) 1(1794.12,1776.73) 1(1794.12,2061.73) 1(1794.12,2066.73) 1(1794.12,2066.73) 1(1800.12,146.73) 1(1800.12,146.73) 1(1800.12,151.73) 1(1800.12,436.73) 1(1800.12,441.73) 1(1800.12,441.73) 1(1800.12,1771.73) 1(1800.12,1771.73) 1(1800.12,1776.73) 1(1800.12,2061.73) 1(1800.12,2066.73) 1(1800.12,2066.73) 1(1813.81,146.73) 1(1813.81,146.73) 1(1813.81,151.73) 1(1813.81,436.73) 1(1813.81,441.73) 1(1813.81,441.73) 1(1813.81,1771.73) 1(1813.81,1771.73) 1(1813.81,1776.73) 1(1813.81,2061.73) 1(1813.81,2066.73) 1(1813.81,2066.73) 1(1819.81,146.73) 1(1819.81,146.73) 1(1819.81,151.73) 1(1819.81,436.73) 1(1819.81,441.73) 1(1819.81,441.73) 1(1819.81,1771.73) 1(1819.81,1771.73) 1(1819.81,1776.73) 1(1819.81,2061.73) 1(1819.81,2066.73) 1(1819.81,2066.73) 1(1833.5,146.73) 1(1833.5,146.73) 1(1833.5,151.73) 1(1833.5,436.73) 1(1833.5,441.73) 1(1833.5,441.73) 1(1833.5,1771.73) 1(1833.5,1771.73) 1(1833.5,1776.73) 1(1833.5,2061.73) 1(1833.5,2066.73) 1(1833.5,2066.73) 1(1839.5,146.73) 1(1839.5,146.73) 1(1839.5,151.73) 1(1839.5,436.73) 1(1839.5,441.73) 1(1839.5,441.73) 1(1839.5,1771.73) 1(1839.5,1771.73) 1(1839.5,1776.73) 1(1839.5,2061.73) 1(1839.5,2066.73) 1(1839.5,2066.73) 1(1853.19,146.73) 1(1853.19,146.73) 1(1853.19,151.73) 1(1853.19,436.73) 1(1853.19,441.73) 1(1853.19,441.73) 1(1853.19,1771.73) 1(1853.19,1771.73) 1(1853.19,1776.73) 1(1853.19,2061.73) 1(1853.19,2066.73) 1(1853.19,2066.73) 1(1857.92,499.37) 1(1857.92,499.37) 1(1857.92,579.37) 1(1857.92,579.37) 1(1859.19,146.73) 1(1859.19,146.73) 1(1859.19,151.73) 1(1859.19,436.73) 1(1859.19,441.73) 1(1859.19,441.73) 1(1859.19,1771.73) 1(1859.19,1771.73) 1(1859.19,1776.73) 1(1859.19,2061.73) 1(1859.19,2066.73) 1(1859.19,2066.73) 1(1872.88,146.73) 1(1872.88,146.73) 1(1872.88,151.73) 1(1872.88,436.73) 1(1872.88,441.73) 1(1872.88,441.73) 1(1872.88,1771.73) 1(1872.88,1771.73) 1(1872.88,1776.73) 1(1872.88,2061.73) 1(1872.88,2066.73) 1(1872.88,2066.73) 1(1878.88,146.73) 1(1878.88,146.73) 1(1878.88,151.73) 1(1878.88,436.73) 1(1878.88,441.73) 1(1878.88,441.73) 1(1878.88,1771.73) 1(1878.88,1771.73) 1(1878.88,1776.73) 1(1878.88,2061.73) 1(1878.88,2066.73) 1(1878.88,2066.73) 1(1892.57,146.73) 1(1892.57,146.73) 1(1892.57,151.73) 1(1892.57,436.73) 1(1892.57,441.73) 1(1892.57,441.73) 1(1892.57,1771.73) 1(1892.57,1771.73) 1(1892.57,1776.73) 1(1892.57,2061.73) 1(1892.57,2066.73) 1(1892.57,2066.73) 1(1894,970) 1(1894,970) 1(1894,1050) 1(1894,1050) 1(1898.57,146.73) 1(1898.57,146.73) 1(1898.57,151.73) 1(1898.57,436.73) 1(1898.57,441.73) 1(1898.57,441.73) 1(1898.57,1771.73) 1(1898.57,1771.73) 1(1898.57,1776.73) 1(1898.57,2061.73) 1(1898.57,2066.73) 1(1898.57,2066.73) 1(1912.26,146.73) 1(1912.26,146.73) 1(1912.26,151.73) 1(1912.26,436.73) 1(1912.26,441.73) 1(1912.26,441.73) 1(1912.26,1771.73) 1(1912.26,1771.73) 1(1912.26,1776.73) 1(1912.26,2061.73) 1(1912.26,2066.73) 1(1912.26,2066.73) 1(1918.26,146.73) 1(1918.26,146.73) 1(1918.26,151.73) 1(1918.26,436.73) 1(1918.26,441.73) 1(1918.26,441.73) 1(1918.26,1771.73) 1(1918.26,1771.73) 1(1918.26,1776.73) 1(1918.26,2061.73) 1(1918.26,2066.73) 1(1918.26,2066.73) 1(1931.95,146.73) 1(1931.95,146.73) 1(1931.95,151.73) 1(1931.95,436.73) 1(1931.95,441.73) 1(1931.95,441.73) 1(1931.95,1771.73) 1(1931.95,1771.73) 1(1931.95,1776.73) 1(1931.95,2061.73) 1(1931.95,2066.73) 1(1931.95,2066.73) 1(1937.95,146.73) 1(1937.95,146.73) 1(1937.95,151.73) 1(1937.95,436.73) 1(1937.95,441.73) 1(1937.95,441.73) 1(1937.95,1771.73) 1(1937.95,1771.73) 1(1937.95,1776.73) 1(1937.95,2061.73) 1(1937.95,2066.73) 1(1937.95,2066.73) 1(1951.64,146.73) 1(1951.64,146.73) 1(1951.64,151.73) 1(1951.64,436.73) 1(1951.64,441.73) 1(1951.64,441.73) 1(1951.64,1771.73) 1(1951.64,1771.73) 1(1951.64,1776.73) 1(1951.64,2061.73) 1(1951.64,2066.73) 1(1951.64,2066.73) 1(1957.64,146.73) 1(1957.64,146.73) 1(1957.64,151.73) 1(1957.64,436.73) 1(1957.64,441.73) 1(1957.64,441.73) 1(1957.64,1771.73) 1(1957.64,1771.73) 1(1957.64,1776.73) 1(1957.64,2061.73) 1(1957.64,2066.73) 1(1957.64,2066.73) 1(1971.33,146.73) 1(1971.33,146.73) 1(1971.33,151.73) 1(1971.33,436.73) 1(1971.33,441.73) 1(1971.33,441.73) 1(1971.33,1771.73) 1(1971.33,1771.73) 1(1971.33,1776.73) 1(1971.33,2061.73) 1(1971.33,2066.73) 1(1971.33,2066.73) 1(1977.33,146.73) 1(1977.33,146.73) 1(1977.33,151.73) 1(1977.33,436.73) 1(1977.33,441.73) 1(1977.33,441.73) 1(1977.33,1771.73) 1(1977.33,1771.73) 1(1977.33,1776.73) 1(1977.33,2061.73) 1(1977.33,2066.73) 1(1977.33,2066.73) 1(1991.02,146.73) 1(1991.02,146.73) 1(1991.02,151.73) 1(1991.02,436.73) 1(1991.02,441.73) 1(1991.02,441.73) 1(1991.02,1771.73) 1(1991.02,1771.73) 1(1991.02,1776.73) 1(1991.02,2061.73) 1(1991.02,2066.73) 1(1991.02,2066.73) 1(1997.02,146.73) 1(1997.02,146.73) 1(1997.02,151.73) 1(1997.02,436.73) 1(1997.02,441.73) 1(1997.02,441.73) 1(1997.02,1771.73) 1(1997.02,1771.73) 1(1997.02,1776.73) 1(1997.02,2061.73) 1(1997.02,2066.73) 1(1997.02,2066.73) 1(2005.92,499.37) 1(2005.92,499.37) 1(2005.92,579.37) 1(2005.92,579.37) 1(2010.71,146.73) 1(2010.71,146.73) 1(2010.71,151.73) 1(2010.71,436.73) 1(2010.71,441.73) 1(2010.71,441.73) 1(2010.71,1771.73) 1(2010.71,1771.73) 1(2010.71,1776.73) 1(2010.71,2061.73) 1(2010.71,2066.73) 1(2010.71,2066.73) 1(2016.71,146.73) 1(2016.71,146.73) 1(2016.71,151.73) 1(2016.71,436.73) 1(2016.71,441.73) 1(2016.71,441.73) 1(2016.71,1771.73) 1(2016.71,1771.73) 1(2016.71,1776.73) 1(2016.71,2061.73) 1(2016.71,2066.73) 1(2016.71,2066.73) 1(2030.4,146.73) 1(2030.4,146.73) 1(2030.4,151.73) 1(2030.4,436.73) 1(2030.4,441.73) 1(2030.4,441.73) 1(2030.4,1771.73) 1(2030.4,1771.73) 1(2030.4,1776.73) 1(2030.4,2061.73) 1(2030.4,2066.73) 1(2030.4,2066.73) 1(2036.4,146.73) 1(2036.4,146.73) 1(2036.4,151.73) 1(2036.4,436.73) 1(2036.4,441.73) 1(2036.4,441.73) 1(2036.4,1771.73) 1(2036.4,1771.73) 1(2036.4,1776.73) 1(2036.4,2061.73) 1(2036.4,2066.73) 1(2036.4,2066.73) 1(2050.09,146.73) 1(2050.09,146.73) 1(2050.09,151.73) 1(2050.09,436.73) 1(2050.09,441.73) 1(2050.09,441.73) 1(2050.09,1771.73) 1(2050.09,1771.73) 1(2050.09,1776.73) 1(2050.09,2061.73) 1(2050.09,2066.73) 1(2050.09,2066.73) 1(2056.09,146.73) 1(2056.09,146.73) 1(2056.09,151.73) 1(2056.09,436.73) 1(2056.09,441.73) 1(2056.09,441.73) 1(2056.09,1771.73) 1(2056.09,1771.73) 1(2056.09,1776.73) 1(2056.09,2061.73) 1(2056.09,2066.73) 1(2056.09,2066.73) 1(2069.78,146.73) 1(2069.78,146.73) 1(2069.78,151.73) 1(2069.78,436.73) 1(2069.78,441.73) 1(2069.78,441.73) 1(2069.78,1771.73) 1(2069.78,1771.73) 1(2069.78,1776.73) 1(2069.78,2061.73) 1(2069.78,2066.73) 1(2069.78,2066.73) 1(2075.78,146.73) 1(2075.78,146.73) 1(2075.78,151.73) 1(2075.78,436.73) 1(2075.78,441.73) 1(2075.78,441.73) 1(2075.78,1771.73) 1(2075.78,1771.73) 1(2075.78,1776.73) 1(2075.78,2061.73) 1(2075.78,2066.73) 1(2075.78,2066.73) 1(2129.52,416.73) 1(2129.52,416.73) 1(2129.52,416.73) 1(2129.52,2041.73) 1(2129.52,2041.73) 1(2129.52,2041.73) 1(2131.92,422.51) 1(2131.92,422.51) 1(2131.92,422.51) 1(2131.92,2047.51) 1(2131.92,2047.51) 1(2131.92,2047.51) 1(2137,428.73) 1(2137,428.73) 1(2137,2053.73) 1(2137,2053.73) 1(2184.52,171.73) 1(2184.52,171.73) 1(2184.52,171.73) 1(2184.52,361.73) 1(2184.52,361.73) 1(2184.52,361.73) 1(2184.52,1796.73) 1(2184.52,1796.73) 1(2184.52,1796.73) 1(2184.52,1986.73) 1(2184.52,1986.73) 1(2184.52,1986.73) 1(2190.3,165.96) 1(2190.3,165.96) 1(2190.3,165.96) 1(2190.3,364.12) 1(2190.3,364.12) 1(2190.3,364.12) 1(2190.3,1790.96) 1(2190.3,1790.96) 1(2190.3,1790.96) 1(2190.3,1989.12) 1(2190.3,1989.12) 1(2190.3,1989.12) 1(2198.02,367.71) 1(2198.02,367.71) 1(2198.02,428.73) 1(2198.02,428.73) 1(2198.02,1992.71) 1(2198.02,1992.71) 1(2198.02,2053.73) 1(2198.02,2053.73) 1(2206.02,151.73) 1(2206.02,151.73) 1(2206.02,436.73) 1(2206.02,436.73) 1(2206.02,1776.73) 1(2206.02,1776.73) 1(2206.02,2061.73) 1(2206.02,2061.73) 1(2326.73,429.22) 1(2326.73,429.22) 1(2326.73,435.22) 1(2326.73,435.22) 1(2326.73,448.91) 1(2326.73,448.91) 1(2326.73,454.91) 1(2326.73,454.91) 1(2326.73,468.6) 1(2326.73,468.6) 1(2326.73,474.6) 1(2326.73,474.6) 1(2326.73,488.29) 1(2326.73,488.29) 1(2326.73,494.29) 1(2326.73,494.29) 1(2326.73,507.98) 1(2326.73,507.98) 1(2326.73,513.98) 1(2326.73,513.98) 1(2326.73,527.67) 1(2326.73,527.67) 1(2326.73,533.67) 1(2326.73,533.67) 1(2326.73,547.36) 1(2326.73,547.36) 1(2326.73,553.36) 1(2326.73,553.36) 1(2326.73,567.05) 1(2326.73,567.05) 1(2326.73,573.05) 1(2326.73,573.05) 1(2326.73,586.74) 1(2326.73,586.74) 1(2326.73,592.74) 1(2326.73,592.74) 1(2326.73,606.43) 1(2326.73,606.43) 1(2326.73,612.43) 1(2326.73,612.43) 1(2326.73,626.12) 1(2326.73,626.12) 1(2326.73,632.12) 1(2326.73,632.12) 1(2326.73,645.81) 1(2326.73,645.81) 1(2326.73,651.81) 1(2326.73,651.81) 1(2326.73,665.5) 1(2326.73,665.5) 1(2326.73,671.5) 1(2326.73,671.5) 1(2326.73,685.19) 1(2326.73,685.19) 1(2326.73,691.19) 1(2326.73,691.19) 1(2326.73,704.88) 1(2326.73,704.88) 1(2326.73,710.88) 1(2326.73,710.88) 1(2326.73,724.57) 1(2326.73,724.57) 1(2326.73,730.57) 1(2326.73,730.57) 1(2326.73,744.26) 1(2326.73,744.26) 1(2326.73,750.26) 1(2326.73,750.26) 1(2326.73,763.95) 1(2326.73,763.95) 1(2326.73,769.95) 1(2326.73,769.95) 1(2326.73,783.64) 1(2326.73,783.64) 1(2326.73,789.64) 1(2326.73,789.64) 1(2326.73,803.33) 1(2326.73,803.33) 1(2326.73,809.33) 1(2326.73,809.33) 1(2326.73,823.02) 1(2326.73,823.02) 1(2326.73,829.02) 1(2326.73,829.02) 1(2326.73,842.71) 1(2326.73,842.71) 1(2326.73,848.71) 1(2326.73,848.71) 1(2326.73,862.4) 1(2326.73,862.4) 1(2326.73,868.4) 1(2326.73,868.4) 1(2326.73,882.09) 1(2326.73,882.09) 1(2326.73,888.09) 1(2326.73,888.09) 1(2326.73,901.78) 1(2326.73,901.78) 1(2326.73,907.78) 1(2326.73,907.78) 1(2326.73,921.47) 1(2326.73,921.47) 1(2326.73,927.47) 1(2326.73,927.47) 1(2326.73,941.16) 1(2326.73,941.16) 1(2326.73,947.16) 1(2326.73,947.16) 1(2326.73,960.85) 1(2326.73,960.85) 1(2326.73,966.85) 1(2326.73,966.85) 1(2326.73,980.54) 1(2326.73,980.54) 1(2326.73,986.54) 1(2326.73,986.54) 1(2326.73,1000.23) 1(2326.73,1000.23) 1(2326.73,1006.23) 1(2326.73,1006.23) 1(2326.73,1216.72) 1(2326.73,1216.72) 1(2326.73,1222.72) 1(2326.73,1222.72) 1(2326.73,1236.41) 1(2326.73,1236.41) 1(2326.73,1242.41) 1(2326.73,1242.41) 1(2326.73,1256.1) 1(2326.73,1256.1) 1(2326.73,1262.1) 1(2326.73,1262.1) 1(2326.73,1275.79) 1(2326.73,1275.79) 1(2326.73,1281.79) 1(2326.73,1281.79) 1(2326.73,1295.48) 1(2326.73,1295.48) 1(2326.73,1301.48) 1(2326.73,1301.48) 1(2326.73,1315.17) 1(2326.73,1315.17) 1(2326.73,1321.17) 1(2326.73,1321.17) 1(2326.73,1334.86) 1(2326.73,1334.86) 1(2326.73,1340.86) 1(2326.73,1340.86) 1(2326.73,1354.55) 1(2326.73,1354.55) 1(2326.73,1360.55) 1(2326.73,1360.55) 1(2326.73,1374.24) 1(2326.73,1374.24) 1(2326.73,1380.24) 1(2326.73,1380.24) 1(2326.73,1393.93) 1(2326.73,1393.93) 1(2326.73,1399.93) 1(2326.73,1399.93) 1(2326.73,1413.62) 1(2326.73,1413.62) 1(2326.73,1419.62) 1(2326.73,1419.62) 1(2326.73,1433.31) 1(2326.73,1433.31) 1(2326.73,1439.31) 1(2326.73,1439.31) 1(2326.73,1453) 1(2326.73,1453) 1(2326.73,1459) 1(2326.73,1459) 1(2326.73,1472.69) 1(2326.73,1472.69) 1(2326.73,1478.69) 1(2326.73,1478.69) 1(2326.73,1492.38) 1(2326.73,1492.38) 1(2326.73,1498.38) 1(2326.73,1498.38) 1(2326.73,1512.07) 1(2326.73,1512.07) 1(2326.73,1518.07) 1(2326.73,1518.07) 1(2326.73,1531.76) 1(2326.73,1531.76) 1(2326.73,1537.76) 1(2326.73,1537.76) 1(2326.73,1551.45) 1(2326.73,1551.45) 1(2326.73,1557.45) 1(2326.73,1557.45) 1(2326.73,1571.14) 1(2326.73,1571.14) 1(2326.73,1577.14) 1(2326.73,1577.14) 1(2326.73,1590.83) 1(2326.73,1590.83) 1(2326.73,1596.83) 1(2326.73,1596.83) 1(2326.73,1610.47) 1(2326.73,1610.47) 1(2326.73,1610.52) 1(2326.73,1610.52) 1(2326.73,1616.47) 1(2326.73,1616.47) 1(2326.73,1616.52) 1(2326.73,1616.52) 1(2326.73,1630.21) 1(2326.73,1630.21) 1(2326.73,1636.21) 1(2326.73,1636.21) 1(2326.73,1649.9) 1(2326.73,1649.9) 1(2326.73,1655.9) 1(2326.73,1655.9) 1(2326.73,1669.59) 1(2326.73,1669.59) 1(2326.73,1675.59) 1(2326.73,1675.59) 1(2326.73,1689.28) 1(2326.73,1689.28) 1(2326.73,1695.28) 1(2326.73,1695.28) 1(2326.73,1708.97) 1(2326.73,1708.97) 1(2326.73,1714.97) 1(2326.73,1714.97) 1(2326.73,1728.66) 1(2326.73,1728.66) 1(2326.73,1734.66) 1(2326.73,1734.66) 1(2326.73,1748.35) 1(2326.73,1748.35) 1(2326.73,1754.35) 1(2326.73,1754.35) 1(2326.73,1768.04) 1(2326.73,1768.04) 1(2326.73,1774.04) 1(2326.73,1774.04) 1(2326.73,1787.73) 1(2326.73,1787.73) 1(2326.73,1793.73) 1(2326.73,1793.73) 1(2331.73,298.98) 1(2331.73,298.98) 1(2331.73,429.22) 1(2331.73,435.22) 1(2331.73,448.91) 1(2331.73,454.91) 1(2331.73,468.6) 1(2331.73,474.6) 1(2331.73,488.29) 1(2331.73,494.29) 1(2331.73,507.98) 1(2331.73,513.98) 1(2331.73,527.67) 1(2331.73,533.67) 1(2331.73,547.36) 1(2331.73,553.36) 1(2331.73,567.05) 1(2331.73,573.05) 1(2331.73,586.74) 1(2331.73,592.74) 1(2331.73,606.43) 1(2331.73,612.43) 1(2331.73,626.12) 1(2331.73,632.12) 1(2331.73,645.81) 1(2331.73,651.81) 1(2331.73,665.5) 1(2331.73,671.5) 1(2331.73,685.19) 1(2331.73,691.19) 1(2331.73,704.88) 1(2331.73,710.88) 1(2331.73,724.57) 1(2331.73,730.57) 1(2331.73,744.26) 1(2331.73,750.26) 1(2331.73,763.95) 1(2331.73,769.95) 1(2331.73,783.64) 1(2331.73,789.64) 1(2331.73,803.33) 1(2331.73,809.33) 1(2331.73,823.02) 1(2331.73,829.02) 1(2331.73,842.71) 1(2331.73,848.71) 1(2331.73,862.4) 1(2331.73,868.4) 1(2331.73,882.09) 1(2331.73,888.09) 1(2331.73,901.78) 1(2331.73,907.78) 1(2331.73,921.47) 1(2331.73,927.47) 1(2331.73,941.16) 1(2331.73,947.16) 1(2331.73,960.85) 1(2331.73,966.85) 1(2331.73,980.54) 1(2331.73,986.54)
